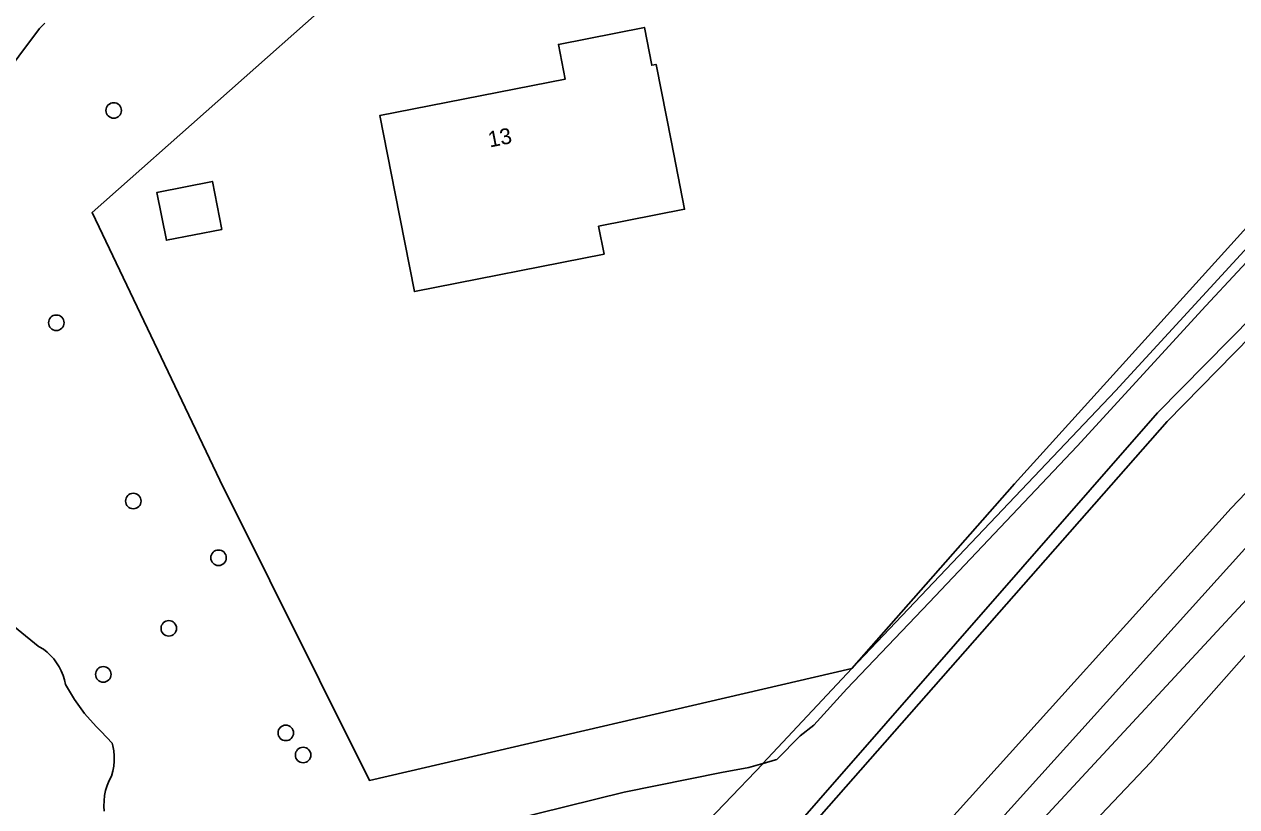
# Model space of a CAD drawing. Extents: x 157663 to 158496, y 379212 to 380934.
# Drawn here: x 158298.5 to 158375, y 380084.4 to 380133.7 of the extents above; entities that cross this region are included whole.
import ezdxf

# ---------------------------------------------------------------- set-up
doc = ezdxf.new("R2010")
doc.units = 0
for name, color, linetype in [('IMGEO_Berm_groen', 7, 'Continuous'), ('IMGEO_Boom', 7, 'Continuous'), ('IMGEO_Groenvoorziening', 7, 'Continuous'), ('IMGEO_Meer_plas_ven_vijver', 7, 'Continuous'), ('IMGEO_Pand', 7, 'Continuous'), ('IMGEO_Pand_nummerreeks', 7, 'Continuous'), ('IMGEO_Voetpad_halfverhard', 7, 'Continuous'), ('IMGEO_Waterloop', 7, 'Continuous')]:
    doc.layers.add(name, color=color, linetype=linetype)

msp = doc.modelspace()

# ---------------------------------------------------------------- linework, layer by layer
at = {"layer": 'IMGEO_Berm_groen'}
msp.add_lwpolyline([(158305.845, 380022.952), (158331.752, 380050.613), (158346.538, 380066.124), (158376.939, 380098.926), (158382.174, 380105.943), (158395.924, 380119.32), (158406.802, 380130.698), (158416.279, 380141.887), (158427.297, 380153.915), (158437.695, 380166.064), (158445.59, 380173.873), (158445.59, 380173.873)], dxfattribs=at)
at = {"layer": 'IMGEO_Boom'}
for centre in [(158304.131, 380128.313), (158300.512, 380114.924), (158305.368, 380103.682), (158310.746, 380100.104), (158307.608, 380095.652), (158303.476, 380092.747), (158314.986, 380089.058), (158316.081, 380087.664)]:
    msp.add_circle(centre, 0.489, dxfattribs=at)
at = {"layer": 'IMGEO_Groenvoorziening'}
for points in [[(158350.695, 380093.122), (158360.95, 380104.759), (158436.002, 380187.68)], [(158436.233, 380185.777), (158436.022, 380185.47), (158428.742, 380177.198), (158420.13, 380167.51), (158412.991, 380159.408), (158405.683, 380151.533), (158404.833, 380149.606), (158403.076, 380148.02), (158401.377, 380147.397), (158395.938, 380141.731), (158388.856, 380134.196), (158382.85, 380127.51), (158367.326, 380110.627), (158350.695, 380093.122)], [(158439.337, 380183.714), (158411.122, 380151.476), (158396.618, 380135.216), (158383.303, 380121.675), (158370.583, 380108.694), (158340.653, 380074.67), (158307.47, 380040.487), (158299.87, 380032.448)], [(158318.727, 380136.148), (158318.621, 380135.936), (158302.772, 380121.88), (158310.837, 380105), (158320.267, 380086.067), (158350.695, 380093.122)], [(158350.695, 380093.122), (158345.083, 380087.129)]]:
    msp.add_lwpolyline(points, dxfattribs=at)
at = {"layer": 'IMGEO_Meer_plas_ven_vijver'}
msp.add_lwpolyline([(158303.533, 380084.119), (158303.512, 380084.447), (158303.52, 380084.776), (158303.557, 380085.104), (158303.624, 380085.426), (158303.719, 380085.741), (158303.841, 380086.047), (158303.991, 380086.34), (158304.076, 380086.65), (158304.132, 380086.966), (158304.16, 380087.285), (158304.16, 380087.606), (158304.13, 380087.926), (158304.073, 380088.241), (158304.027, 380088.42), (158303.337, 380089.153), (158303.019, 380089.471), (158302.296, 380090.291), (158301.649, 380091.172), (158301.083, 380092.107), (158301.023, 380092.4), (158300.938, 380092.687), (158300.827, 380092.965), (158300.691, 380093.232), (158300.533, 380093.486), (158300.352, 380093.724), (158300.151, 380093.946), (158299.931, 380094.149), (158299.693, 380094.331), (158299.44, 380094.491), (158299.374, 380094.528), (158295.802, 380097.419)], dxfattribs=at)
at = {"layer": 'IMGEO_Pand'}
for points in [[(158339.312, 380126.311), (158340.146, 380122.079), (158334.717, 380121.01), (158335.063, 380119.25), (158323.099, 380116.893), (158321.88, 380123.081), (158320.914, 380127.986), (158332.616, 380130.291), (158332.185, 380132.48), (158337.608, 380133.549), (158338.078, 380131.163), (158338.346, 380131.216), (158339.312, 380126.311)], [(158310.956, 380120.815), (158310.362, 380123.833), (158306.859, 380123.143), (158307.453, 380120.125), (158310.956, 380120.815)]]:
    msp.add_lwpolyline(points, dxfattribs=at)
at = {"layer": 'IMGEO_Voetpad_halfverhard'}
for points in [[(158467.874, 380205.318), (158441.375, 380176.227), (158419.7, 380151.493), (158398.889, 380128.586), (158374.632, 380103.233), (158356.557, 380083.229), (158343.864, 380068.969), (158334.417, 380059.036), (158324.122, 380048.333), (158306.701, 380030.411)], [(158443.87, 380175.489), (158443.13, 380174.684), (158421.483, 380149.885), (158400.569, 380126.856), (158376.274, 380101.52), (158358.23, 380081.535), (158345.664, 380067.502), (158336.215, 380057.388), (158325.744, 380046.609), (158308.359, 380028.676)], [(158287.89, 380118.02), (158299.457, 380133.487), (158299.471, 380133.502), (158299.793, 380133.82)]]:
    msp.add_lwpolyline(points, dxfattribs=at)
at = {"layer": 'IMGEO_Waterloop'}
for points in [[(158299.01, 380032.899), (158306.869, 380041.001), (158340.089, 380075.086), (158369.978, 380109.249), (158383.587, 380123.035), (158394.068, 380133.573), (158414.408, 380156.292), (158426.107, 380169.72), (158433.048, 380177.821), (158435.937, 380180.569), (158439.337, 380184.818)], [(158435.739, 380184.139), (158429.223, 380176.773), (158417.807, 380163.601), (158412.368, 380157.425), (158407.156, 380151.419), (158405.711, 380149.691), (158405.173, 380148.842), (158403.926, 380147.85), (158402.652, 380147.284), (158401.66, 380146.66), (158391.66, 380135.896), (158387.014, 380130.995), (158373.02, 380115.981), (158364.918, 380107.142), (158355.57, 380097.284), (158350.386, 380091.845), (158348.29, 380089.551), (158347.44, 380088.871), (158345.961, 380087.383), (158345.883, 380087.353), (158345.102, 380087.134)], [(158314.801, 380029.326), (158335.042, 380049.89), (158363.296, 380080.618), (158369.541, 380087.191), (158378.645, 380097.496), (158383.964, 380104.592), (158387.646, 380107.551), (158408.732, 380128.937), (158418.239, 380139.626), (158428.937, 380152.474), (158435.221, 380159.462), (158439.466, 380164.183), (158446.21, 380170.141)], [(158345.083, 380087.129), (158344.194, 380086.879), (158342.469, 380086.558), (158336.333, 380085.33), (158329.023, 380083.521), (158321.668, 380081.901), (158312.839, 380080.115), (158311.107, 380079.623), (158308.034, 380078.75), (158306.543, 380078.327), (158306.428, 380078.28), (158305.834, 380078.077), (158305.224, 380077.927), (158304.603, 380077.832), (158303.977, 380077.793), (158303.345, 380077.811)], [(158345.102, 380087.134), (158340.189, 380082.006)], [(158345.102, 380087.134), (158345.083, 380087.129)]]:
    msp.add_lwpolyline(points, dxfattribs=at)

# ---------------------------------------------------------------- texts
at = {"layer": 'IMGEO_Pand_nummerreeks'}
msp.add_text('13', height=1, rotation=11.14318, dxfattribs=at).set_placement((158327.853, 380125.975))

doc.saveas('drawing.dxf')
